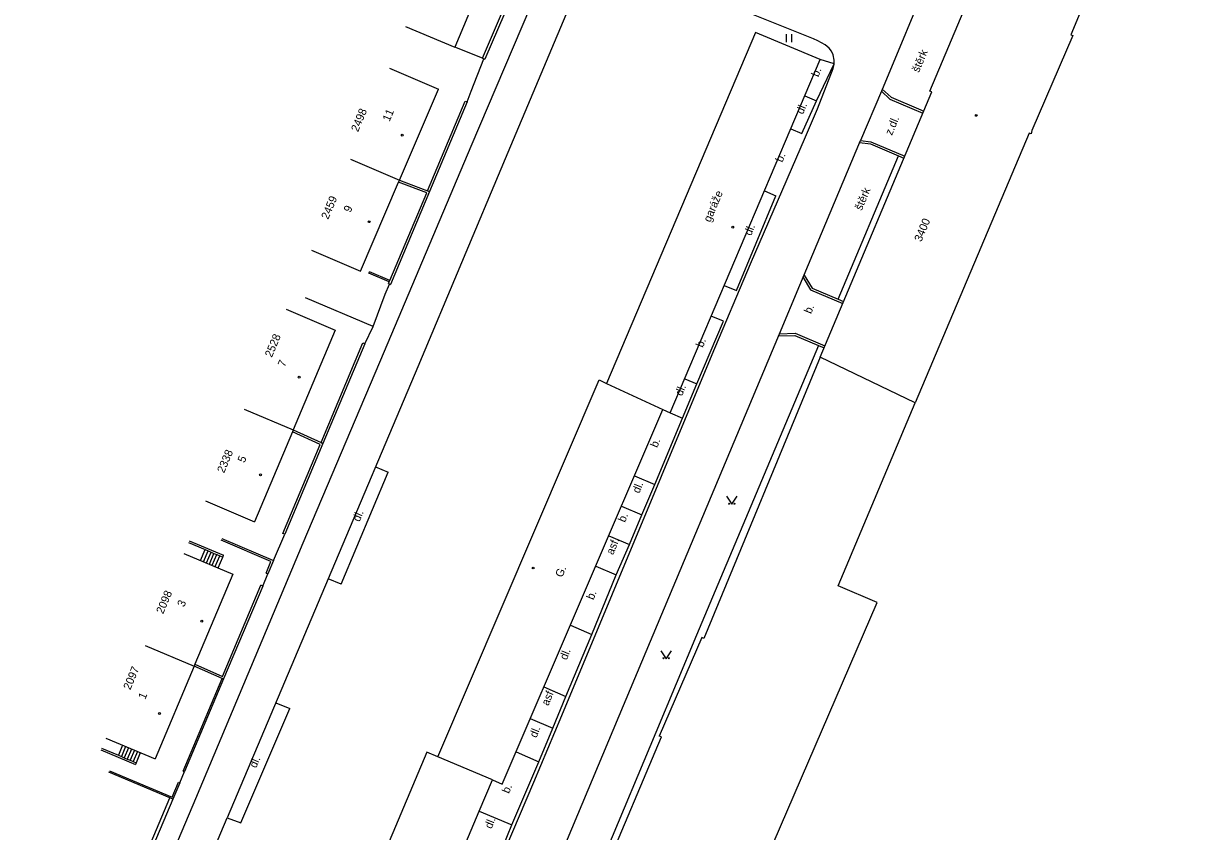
# Model space of a CAD drawing. Extents: x -584400 to -581602, y -1210894 to -1208793.
# Drawn here: x -582495.1 to -582386.2, y -1210231.6 to -1210155.9 of the extents above; entities that cross this region are included whole.
import ezdxf

# ---------------------------------------------------------------- set-up
doc = ezdxf.new("R2010")
doc.units = 0
for name, color, linetype in [('BUDOVY_MĚŘ', 7, 'Continuous'), ('BUDOVY_NEMĚŘ', 7, 'Continuous'), ('POMOC_POPIS', 7, 'Continuous'), ('ROZHRANÍ_PLOCH', 7, 'Continuous'), ('ZN_BUDOV', 7, 'Continuous'), ('ZN_DOPLŇKOVÉ', 7, 'Continuous'), ('ZN_KULTUR', 7, 'Continuous'), ('Č_POPIS_EVID', 7, 'Continuous')]:
    doc.layers.add(name, color=color, linetype=linetype)

msp = doc.modelspace()

# ---------------------------------------------------------------- linework, layer by layer
at = {"layer": 'BUDOVY_MĚŘ'}
for points in [[(-582390.76, -1210129.4), (-582386.2, -1210131.31), (-582387.18, -1210133.65), (-582391.44, -1210143.9), (-582392.25, -1210145.84), (-582396.88, -1210156.94), (-582396.7, -1210157.02), (-582400.53, -1210165.91)], [(-582459.59, -1210146.84), (-582451.37, -1210150.34), (-582454.61, -1210158.1)], [(-582410.09, -1210162.22), (-582406.27, -1210153.16)], [(-582459.23, -1210156.18), (-582454.61, -1210158.1)], [(-582426.42, -1210156.72), (-582440.39, -1210189.61)], [(-582420.38, -1210159.27), (-582426.42, -1210156.72)], [(-582434.42, -1210192.37), (-582420.38, -1210159.27)], [(-582460.75, -1210160.07), (-582456.15, -1210162.04)], [(-582459.81, -1210170.58), (-582456.15, -1210162.04)], [(-582420.38, -1210187.16), (-582409.91, -1210162.3)], [(-582409.91, -1210162.3), (-582410.09, -1210162.22)], [(-582400.53, -1210165.91), (-582400.61, -1210166.23), (-582400.8, -1210166.15), (-582411.48, -1210191.43), (-582420.38, -1210187.16)], [(-582464.4, -1210168.61), (-582459.81, -1210170.58)], [(-582468.05, -1210177.13), (-582463.45, -1210179.1), (-582459.89, -1210170.76), (-582459.81, -1210170.58)], [(-582470.44, -1210182.67), (-582465.83, -1210184.61), (-582469.76, -1210193.97)], [(-582456.2, -1210224.61), (-582441.09, -1210189.29), (-582440.39, -1210189.61)], [(-582440.39, -1210189.61), (-582435.11, -1210192.05)], [(-582474.37, -1210192.03), (-582469.76, -1210193.97)], [(-582451.08, -1210226.76), (-582450.18, -1210227.17), (-582435.11, -1210192.05)], [(-582435.11, -1210192.05), (-582434.42, -1210192.37)], [(-582469.76, -1210193.97), (-582469.84, -1210194.16), (-582473.38, -1210202.57)], [(-582477.98, -1210200.63), (-582473.38, -1210202.57)], [(-582480.02, -1210205.54), (-582475.41, -1210207.48), (-582478.98, -1210215.93), (-582479.05, -1210216.1)], [(-582483.65, -1210214.16), (-582479.05, -1210216.1)], [(-582479.05, -1210216.1), (-582482.71, -1210224.8)], [(-582487.32, -1210222.86), (-582482.71, -1210224.8)], [(-582446.07, -1210248.34), (-582435.26, -1210222.74), (-582435.45, -1210222.66)], [(-582456.2, -1210224.61), (-582457.25, -1210224.17), (-582468.59, -1210251.05), (-582462.44, -1210253.62)], [(-582451.08, -1210226.76), (-582456.2, -1210224.61)], [(-582452.32, -1210229.69), (-582451.08, -1210226.76)], [(-582453.58, -1210232.66), (-582452.32, -1210229.69)]]:
    msp.add_lwpolyline(points, dxfattribs=at)
at = {"layer": 'BUDOVY_NEMĚŘ'}
for points in [[(-582420.38, -1210187.16), (-582431.28, -1210213.53), (-582431.48, -1210213.43), (-582435.45, -1210222.66)], [(-582446.07, -1210248.34), (-582436.95, -1210252.14), (-582431.96, -1210240.29), (-582430.97, -1210237.93), (-582424.5, -1210240.59), (-582422.35, -1210235.37), (-582425.38, -1210234.11), (-582415.02, -1210210.15), (-582418.69, -1210208.59), (-582411.48, -1210191.43)]]:
    msp.add_lwpolyline(points, dxfattribs=at)
at = {"layer": 'ROZHRANÍ_PLOCH'}
for points in [[(-582446, -1210150.66), (-582453.12, -1210167.43), (-582461.23, -1210186.61), (-582468.85, -1210204.58), (-582478.93, -1210228.54), (-582486.73, -1210246.99), (-582493.3, -1210262.56), (-582493.73, -1210263.47), (-582494.23, -1210264.35), (-582495.07, -1210265.54)], [(-582409.98, -1210151.02), (-582414.63, -1210162.24)], [(-582443.46, -1210153.26), (-582449.9, -1210168.58), (-582458.08, -1210188.05), (-582466.48, -1210207.92)], [(-582451.23, -1210236.45), (-582447.22, -1210226.98), (-582444.6, -1210220.72), (-582430.5, -1210186.92), (-582426.91, -1210178.41), (-582421.74, -1210166.52), (-582420.62, -1210163.87), (-582419.16, -1210160.1), (-582419.06, -1210159.72), (-582419.05, -1210159.33), (-582419.14, -1210158.83), (-582419.3, -1210158.49), (-582419.52, -1210158.19), (-582419.9, -1210157.88), (-582420.58, -1210157.51), (-582420.99, -1210157.33), (-582427.25, -1210154.84)], [(-582420.71, -1210163.14), (-582419.07, -1210159.66)], [(-582419.07, -1210159.66), (-582420.38, -1210159.27)], [(-582421.82, -1210162.67), (-582420.71, -1210163.14)], [(-582414.63, -1210162.24), (-582416.6, -1210166.84)], [(-582422.08, -1210166.21), (-582420.71, -1210163.14)], [(-582423.13, -1210165.76), (-582422.08, -1210166.21)], [(-582424.19, -1210184.96), (-582422.28, -1210180.4), (-582416.6, -1210166.84)], [(-582418.69, -1210181.72), (-582413.03, -1210168.29)], [(-582413.03, -1210168.29), (-582412.52, -1210168.5)], [(-582425.6, -1210171.58), (-582424.53, -1210172.04)], [(-582429.36, -1210180.44), (-582428.23, -1210180.92), (-582424.53, -1210172.04)], [(-582421.98, -1210179.69), (-582421.27, -1210180.85), (-582418.26, -1210182.12)], [(-582421.88, -1210179.47), (-582421.13, -1210180.69), (-582418.69, -1210181.72)], [(-582418.69, -1210181.72), (-582418.18, -1210181.94)], [(-582431.92, -1210189.66), (-582429.43, -1210183.79), (-582430.58, -1210183.3)], [(-582450.23, -1210258.23), (-582450.65, -1210259.44), (-582451.18, -1210259.01), (-582451.66, -1210258.51), (-582452.07, -1210257.97), (-582452.42, -1210257.37), (-582452.7, -1210256.74), (-582452.9, -1210256.09), (-582453.03, -1210255.41), (-582453.08, -1210254.73), (-582453.04, -1210254.04), (-582452.93, -1210253.36), (-582452.74, -1210252.7), (-582452.37, -1210251.86), (-582449.07, -1210244.24), (-582439.21, -1210220.76), (-582424.19, -1210184.96)], [(-582424.27, -1210185.16), (-582422.75, -1210185.12), (-582420.52, -1210186.06)], [(-582424.19, -1210184.96), (-582422.71, -1210184.92), (-582419.93, -1210186.09)], [(-582420.52, -1210186.06), (-582431.95, -1210213.2), (-582435.77, -1210222.33), (-582445.08, -1210244.55)], [(-582420.52, -1210186.06), (-582420.01, -1210186.28)], [(-582433.29, -1210192.86), (-582431.92, -1210189.66)], [(-582433.07, -1210189.17), (-582431.92, -1210189.66)], [(-582434.42, -1210192.37), (-582433.29, -1210192.86)], [(-582435.87, -1210199.1), (-582433.29, -1210192.86)], [(-582462.05, -1210197.43), (-582460.87, -1210197.93)], [(-582465.26, -1210208.42), (-582460.87, -1210197.93)], [(-582437.79, -1210198.28), (-582435.87, -1210199.1)], [(-582437.09, -1210201.94), (-582435.87, -1210199.1)], [(-582439, -1210201.12), (-582437.09, -1210201.94)], [(-582438.25, -1210204.72), (-582437.09, -1210201.94)], [(-582479.52, -1210204.36), (-582476.3, -1210205.72)], [(-582440.19, -1210203.89), (-582438.25, -1210204.72)], [(-582479.59, -1210204.52), (-582478.03, -1210205.18)], [(-582478.45, -1210206.2), (-582478.03, -1210205.18)], [(-582478.18, -1210206.32), (-582477.75, -1210205.3)], [(-582478.03, -1210205.18), (-582477.75, -1210205.3)], [(-582477.9, -1210206.43), (-582477.47, -1210205.42)], [(-582477.75, -1210205.3), (-582477.47, -1210205.42)], [(-582477.47, -1210205.42), (-582477.19, -1210205.54)], [(-582439.49, -1210207.55), (-582438.25, -1210204.72)], [(-582477.62, -1210206.55), (-582477.19, -1210205.54)], [(-582477.35, -1210206.66), (-582476.92, -1210205.65)], [(-582477.19, -1210205.54), (-582476.92, -1210205.65)], [(-582477.07, -1210206.78), (-582476.64, -1210205.77)], [(-582476.92, -1210205.65), (-582476.64, -1210205.77)], [(-582476.79, -1210206.9), (-582476.37, -1210205.88)], [(-582476.64, -1210205.77), (-582476.37, -1210205.88)], [(-582476.37, -1210205.88), (-582476.3, -1210205.72)], [(-582441.78, -1210213.14), (-582439.49, -1210207.55)], [(-582441.41, -1210206.73), (-582439.49, -1210207.55)], [(-582466.48, -1210207.92), (-582475.95, -1210230.32)], [(-582465.26, -1210208.42), (-582466.48, -1210207.92)], [(-582443.79, -1210212.28), (-582441.78, -1210213.14)], [(-582444.22, -1210218.94), (-582441.78, -1210213.14)], [(-582446.27, -1210218.06), (-582444.22, -1210218.94)], [(-582471.39, -1210219.53), (-582470.08, -1210220.09)], [(-582445.44, -1210221.92), (-582444.22, -1210218.94)], [(-582475.95, -1210230.32), (-582474.68, -1210230.8), (-582470.08, -1210220.09)], [(-582447.54, -1210221.02), (-582445.44, -1210221.92)], [(-582446.75, -1210225.06), (-582445.44, -1210221.92)], [(-582487.79, -1210223.96), (-582484.56, -1210225.32)], [(-582487.72, -1210223.8), (-582486.15, -1210224.46)], [(-582485.75, -1210223.52), (-582486.15, -1210224.46)], [(-582485.48, -1210223.63), (-582485.87, -1210224.58)], [(-582485.2, -1210223.75), (-582485.6, -1210224.69)], [(-582484.92, -1210223.87), (-582485.32, -1210224.81)], [(-582486.15, -1210224.46), (-582485.87, -1210224.58)], [(-582485.87, -1210224.58), (-582485.6, -1210224.69)], [(-582485.6, -1210224.69), (-582485.32, -1210224.81)], [(-582485.32, -1210224.81), (-582485.04, -1210224.93)], [(-582484.65, -1210223.98), (-582485.04, -1210224.93)], [(-582485.04, -1210224.93), (-582484.77, -1210225.04)], [(-582484.37, -1210224.1), (-582484.77, -1210225.04)], [(-582484.77, -1210225.04), (-582484.49, -1210225.16)], [(-582484.1, -1210224.22), (-582484.49, -1210225.16)], [(-582448.88, -1210224.15), (-582446.75, -1210225.06)], [(-582484.49, -1210225.16), (-582484.56, -1210225.32)], [(-582449.28, -1210230.97), (-582446.75, -1210225.06)], [(-582490.56, -1210265.02), (-582483.41, -1210248), (-582475.95, -1210230.32)], [(-582452.32, -1210229.69), (-582449.28, -1210230.97)], [(-582450.5, -1210233.96), (-582449.28, -1210230.97)]]:
    msp.add_lwpolyline(points, dxfattribs=at)
at = {"layer": 'ZN_BUDOV'}
for centre in [(-582405.74, -1210164.5), (-582459.54, -1210166.35), (-582462.65, -1210174.46), (-582428.57, -1210174.98), (-582469.2, -1210189.02), (-582472.83, -1210198.18), (-582447.27, -1210206.91), (-582478.34, -1210211.9), (-582482.29, -1210220.54)]:
    msp.add_circle(centre, 0.0875, dxfattribs=at)
at = {"layer": 'ZN_DOPLŇKOVÉ'}
for points in [[(-582458.62, -1210144.66), (-582458.52, -1210144.43), (-582447.47, -1210149.13), (-582451.79, -1210159.24)], [(-582452.02, -1210159.15), (-582447.8, -1210149.26), (-582458.62, -1210144.66)], [(-582452.02, -1210159.15), (-582454.61, -1210158.1)], [(-582453.09, -1210162.24), (-582451.91, -1210159.19)], [(-582452.02, -1210159.15), (-582451.79, -1210159.24)], [(-582453.45, -1210163.23), (-582453.09, -1210162.24)], [(-582414.63, -1210162.24), (-582413.84, -1210162.97)], [(-582414.55, -1210162.04), (-582413.73, -1210162.8)], [(-582413.84, -1210162.97), (-582410.74, -1210164.28)], [(-582413.73, -1210162.8), (-582411.17, -1210163.88)], [(-582457.17, -1210171.56), (-582453.64, -1210163.16)], [(-582453.64, -1210163.16), (-582453.45, -1210163.23), (-582456.98, -1210171.63)], [(-582411.17, -1210163.88), (-582410.67, -1210164.09)], [(-582416.68, -1210167.03), (-582415.67, -1210167.18)], [(-582416.6, -1210166.84), (-582415.61, -1210166.99)], [(-582415.67, -1210167.18), (-582413.03, -1210168.29)], [(-582415.61, -1210166.99), (-582412.45, -1210168.32)], [(-582459.81, -1210170.58), (-582457.17, -1210171.56)], [(-582460.71, -1210179.97), (-582457.25, -1210171.75), (-582459.89, -1210170.76)], [(-582457.17, -1210171.56), (-582456.98, -1210171.63), (-582460.65, -1210180.34)], [(-582460.77, -1210180.11), (-582462.69, -1210179.29), (-582462.63, -1210179.15)], [(-582460.71, -1210179.97), (-582462.63, -1210179.15)], [(-582461.16, -1210181.24), (-582460.74, -1210180.3)], [(-582460.83, -1210180.26), (-582460.77, -1210180.11)], [(-582460.83, -1210180.26), (-582460.65, -1210180.34)], [(-582460.77, -1210180.11), (-582460.71, -1210179.97)], [(-582462.27, -1210184.27), (-582461.16, -1210181.24)], [(-582462.27, -1210184.27), (-582468.62, -1210181.59)], [(-582463.05, -1210185.9), (-582462.27, -1210184.27)], [(-582467.16, -1210195.15), (-582463.23, -1210185.82)], [(-582463.23, -1210185.82), (-582463.05, -1210185.9), (-582466.98, -1210195.23)], [(-582470.74, -1210203.68), (-582467.24, -1210195.33), (-582469.84, -1210194.16)], [(-582469.76, -1210193.97), (-582467.16, -1210195.15)], [(-582467.16, -1210195.15), (-582466.98, -1210195.23), (-582470.55, -1210203.75), (-582470.74, -1210203.68)], [(-582472.31, -1210207.39), (-582471.85, -1210206.29), (-582476.51, -1210204.31)], [(-582476.44, -1210204.15), (-582471.61, -1210206.2), (-582472.14, -1210207.46)], [(-582471.61, -1210206.2), (-582470.55, -1210203.75)], [(-582472.62, -1210208.6), (-582472.14, -1210207.46)], [(-582472.31, -1210207.39), (-582472.14, -1210207.46)], [(-582478.98, -1210215.93), (-582476.39, -1210217.07), (-582472.79, -1210208.53)], [(-582472.62, -1210208.6), (-582476.29, -1210217.31), (-582476.43, -1210217.25)], [(-582472.62, -1210208.6), (-582472.79, -1210208.53)], [(-582476.43, -1210217.25), (-582479.05, -1210216.1)], [(-582480.09, -1210225.94), (-582476.43, -1210217.25)], [(-582476.29, -1210217.31), (-582479.95, -1210225.99)], [(-582481.32, -1210228.45), (-582487.04, -1210226.05)], [(-582486.98, -1210225.92), (-582481.12, -1210228.37), (-582480.53, -1210226.97)], [(-582480.4, -1210227.03), (-582479.95, -1210225.99)], [(-582480.09, -1210225.94), (-582479.95, -1210225.99)], [(-582480.53, -1210226.97), (-582480.4, -1210227.03), (-582481.04, -1210228.57), (-582481.32, -1210228.45)], [(-582481.04, -1210228.57), (-582488.6, -1210246.48), (-582493.2, -1210244.53)], [(-582493.09, -1210244.26), (-582488.76, -1210246.08), (-582481.32, -1210228.45)]]:
    msp.add_lwpolyline(points, dxfattribs=at)
at = {"layer": 'ZN_KULTUR'}
for p, q in [((-582423.54, -1210157.65), (-582423.54, -1210156.9)), ((-582423.04, -1210157.65), (-582423.04, -1210156.9))]:
    msp.add_line(p, q, dxfattribs=at)
for points in [[(-582429.16, -1210200.19), (-582428.66, -1210200.94), (-582428.16, -1210200.19)], [(-582435.31, -1210214.67), (-582434.81, -1210215.42), (-582434.31, -1210214.67)]]:
    msp.add_lwpolyline(points, dxfattribs=at)
for centre in [(-582428.91, -1210200.89), (-582428.41, -1210200.89), (-582435.06, -1210215.37), (-582434.56, -1210215.37)]:
    msp.add_circle(centre, 0.05, dxfattribs=at)

# ---------------------------------------------------------------- texts
at = {"layer": 'POMOC_POPIS'}
for s, rotation, p in [('štěrk', 67.1568, (-582411.12, -1210160.53)), ('b.', 67.803, (-582420.55, -1210160.95)), ('dl.', 67.803, (-582421.98, -1210164.45)), ('z.dl.', 67.1568, (-582413.65, -1210166.43)), ('b.', 67.8033, (-582423.92, -1210168.95)), ('garáže', 67.0149, (-582430.67, -1210174.56)), ('štěrk', 67.1568, (-582416.48, -1210173.46)), ('dl.', 67.8033, (-582426.85, -1210175.83)), ('b.', 67.1621, (-582421.23, -1210183.15)), ('b.', 67.8033, (-582431.37, -1210186.31)), ('dl.', 67.8033, (-582433.32, -1210190.85)), ('b.', 67.8033, (-582435.65, -1210195.69)), ('dl.', 67.8033, (-582437.33, -1210199.97)), ('dl.', 66.7188, (-582463.56, -1210202.63)), ('b.', 67.8033, (-582438.67, -1210202.69)), ('asf.', 67.8033, (-582439.78, -1210205.73)), ('G.', 66.3788, (-582444.56, -1210207.85)), ('b.', 67.8033, (-582441.63, -1210209.95)), ('dl.', 67.8033, (-582444.14, -1210215.59)), ('asf.', 67.8033, (-582445.85, -1210219.87)), ('dl.', 67.8033, (-582446.97, -1210222.87)), ('dl.', 66.7188, (-582473.24, -1210225.71)), ('b.', 67.8033, (-582449.54, -1210228.1)), ('dl.', 67.8033, (-582451.18, -1210231.4))]:
    msp.add_text(s, height=0.75, rotation=rotation, dxfattribs=at).set_placement(p)
at = {"layer": 'Č_POPIS_EVID'}
for s, rotation, p in [('2498', 67.3198, (-582463.69, -1210166.1)), ('11', 66.8217, (-582460.74, -1210165.13)), ('2459', 67, (-582466.49, -1210174.3)), ('9', 66.8233, (-582464.39, -1210173.65)), ('3400', 67.0975, (-582410.9, -1210176.4)), ('2528', 67.203, (-582471.77, -1210187.23)), ('7', 67.203, (-582470.56, -1210188.13)), ('2338', 67, (-582476.25, -1210198.07)), ('5', 67.1991, (-582474.33, -1210197.1)), ('2098', 67, (-582481.96, -1210211.27)), ('3', 67.1393, (-582479.99, -1210210.62)), ('2097', 67.1416, (-582485.04, -1210218.39)), ('1', 67.1416, (-582483.64, -1210219.28))]:
    msp.add_text(s, height=0.75, rotation=rotation, dxfattribs=at).set_placement(p)

doc.saveas('drawing.dxf')
